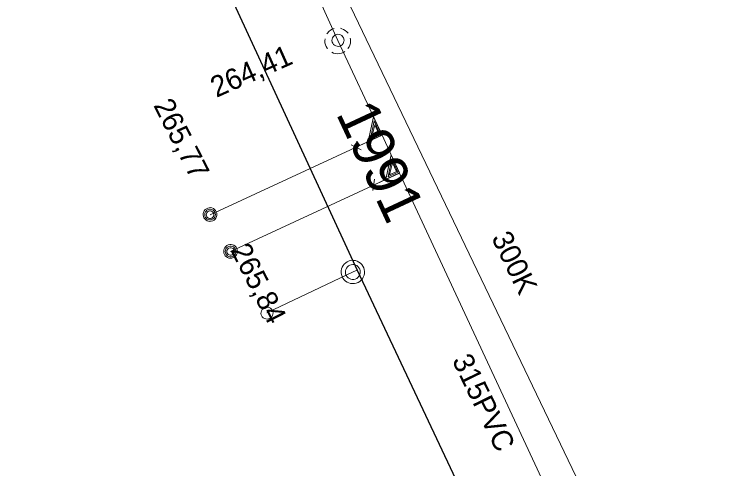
# Model space of a CAD drawing. Extents: x -732096 to -731933, y -1048703 to -1047964.
# Drawn here: x -732047.25 to -732019.99, y -1048499.57 to -1048482.15 of the extents above; entities that cross this region are included whole.
import ezdxf

# ---------------------------------------------------------------- set-up
doc = ezdxf.new("R2010")
doc.units = 0
doc.header["$LTSCALE"] = 0.32
doc.layers.add('1', color=7, linetype='Continuous')
for name, color, linetype, lineweight in [('18', 7, 'Continuous', 13), ('20', 7, 'Continuous', 13), ('49', 7, 'Continuous', 13), ('8', 7, 'Continuous', 13)]:
    doc.layers.add(name, color=color, linetype=linetype, lineweight=lineweight)

msp = doc.modelspace()

# ---------------------------------------------------------------- linework, layer by layer
at = {"layer": '18'}
for p, q in [((-732034.323, -1048487.152), (-732033.938, -1048487.342)), ((-732034.168, -1048487.454), (-732034.103, -1048487.015)), ((-732033.648, -1048488.603), (-732033.262, -1048488.794)), ((-732033.493, -1048488.905), (-732033.428, -1048488.466))]:
    msp.add_line(p, q, dxfattribs=at)
for points in [[(-732034.982, -1048482.697), (-732035.053, -1048482.725), (-732035.12, -1048482.764), (-732035.18, -1048482.812), (-732035.231, -1048482.869), (-732035.255, -1048482.903)], [(-732034.441, -1048482.88), (-732034.491, -1048482.822), (-732034.549, -1048482.772), (-732034.614, -1048482.731), (-732034.685, -1048482.702), (-732034.734, -1048482.688)], [(-732035.327, -1048483.089), (-732035.333, -1048483.166), (-732035.328, -1048483.243), (-732035.311, -1048483.318), (-732035.282, -1048483.389), (-732035.242, -1048483.455), (-732035.226, -1048483.477)], [(-732034.446, -1048483.466), (-732034.405, -1048483.401), (-732034.374, -1048483.331), (-732034.355, -1048483.256), (-732034.347, -1048483.18), (-732034.352, -1048483.103), (-732034.358, -1048483.068)], [(-732035.069, -1048483.606), (-732034.999, -1048483.637), (-732034.924, -1048483.656), (-732034.848, -1048483.663), (-732034.771, -1048483.658), (-732034.696, -1048483.641), (-732034.624, -1048483.613), (-732034.564, -1048483.578)], [(-732034.138, -1048487.244), (-732033.144, -1048486.781), (-732033.47, -1048486.082), (-732033.668, -1048487.025)], [(-732033.583, -1048486.929), (-732033.206, -1048486.753), (-732033.444, -1048486.241), (-732033.584, -1048486.929)], [(-732033.527, -1048486.851), (-732033.263, -1048486.728), (-732033.419, -1048486.392), (-732033.526, -1048486.853)], [(-732033.463, -1048488.695), (-732032.469, -1048488.232), (-732032.795, -1048487.533), (-732032.993, -1048488.476)], [(-732032.908, -1048488.38), (-732032.531, -1048488.204), (-732032.769, -1048487.692), (-732032.909, -1048488.381)], [(-732032.852, -1048488.302), (-732032.588, -1048488.179), (-732032.744, -1048487.843), (-732032.851, -1048488.304)]]:
    msp.add_lwpolyline(points, dxfattribs=at)
for points in [[(-732034.598, -1048483.149), (-732034.604, -1048483.097), (-732034.622, -1048483.047), (-732034.65, -1048483.003), (-732034.688, -1048482.966), (-732034.733, -1048482.939), (-732034.783, -1048482.923), (-732034.835, -1048482.918), (-732034.887, -1048482.925), (-732034.936, -1048482.944), (-732034.98, -1048482.974), (-732035.015, -1048483.013), (-732035.041, -1048483.058), (-732035.056, -1048483.109), (-732035.059, -1048483.161), (-732035.051, -1048483.213), (-732035.03, -1048483.261), (-732035, -1048483.304), (-732034.96, -1048483.339), (-732034.914, -1048483.363), (-732034.863, -1048483.377), (-732034.811, -1048483.379), (-732034.759, -1048483.369), (-732034.711, -1048483.347), (-732034.669, -1048483.315), (-732034.636, -1048483.275), (-732034.612, -1048483.228), (-732034.6, -1048483.177)], [(-732039.475, -1048489.827), (-732039.48, -1048489.771), (-732039.497, -1048489.718), (-732039.526, -1048489.669), (-732039.565, -1048489.628), (-732039.61, -1048489.596), (-732039.663, -1048489.574), (-732039.718, -1048489.563), (-732039.774, -1048489.565), (-732039.828, -1048489.578), (-732039.879, -1048489.603), (-732039.924, -1048489.638), (-732039.96, -1048489.681), (-732039.985, -1048489.731), (-732040, -1048489.786), (-732040.002, -1048489.842), (-732039.994, -1048489.897), (-732039.973, -1048489.95), (-732039.941, -1048489.996), (-732039.901, -1048490.035), (-732039.853, -1048490.065), (-732039.801, -1048490.084), (-732039.745, -1048490.091), (-732039.688, -1048490.087), (-732039.634, -1048490.07), (-732039.585, -1048490.043), (-732039.544, -1048490.005), (-732039.511, -1048489.96), (-732039.487, -1048489.909), (-732039.475, -1048489.854)], [(-732039.534, -1048489.83), (-732039.539, -1048489.781), (-732039.558, -1048489.735), (-732039.585, -1048489.694), (-732039.622, -1048489.661), (-732039.666, -1048489.639), (-732039.715, -1048489.627), (-732039.764, -1048489.627), (-732039.811, -1048489.639), (-732039.855, -1048489.662), (-732039.892, -1048489.695), (-732039.921, -1048489.736), (-732039.938, -1048489.783), (-732039.943, -1048489.832), (-732039.936, -1048489.881), (-732039.919, -1048489.927), (-732039.891, -1048489.967), (-732039.853, -1048490), (-732039.809, -1048490.022), (-732039.761, -1048490.034), (-732039.712, -1048490.033), (-732039.664, -1048490.021), (-732039.62, -1048489.997), (-732039.583, -1048489.964), (-732039.556, -1048489.923), (-732039.539, -1048489.876)], [(-732039.593, -1048489.834), (-732039.598, -1048489.792), (-732039.615, -1048489.754), (-732039.644, -1048489.723), (-732039.678, -1048489.7), (-732039.718, -1048489.689), (-732039.761, -1048489.689), (-732039.801, -1048489.701), (-732039.835, -1048489.724), (-732039.862, -1048489.756), (-732039.879, -1048489.794), (-732039.884, -1048489.835), (-732039.879, -1048489.877), (-732039.86, -1048489.914), (-732039.833, -1048489.946), (-732039.796, -1048489.968), (-732039.757, -1048489.979), (-732039.715, -1048489.978), (-732039.674, -1048489.965), (-732039.641, -1048489.942), (-732039.614, -1048489.909), (-732039.598, -1048489.871)], [(-732038.685, -1048491.237), (-732038.691, -1048491.181), (-732038.708, -1048491.128), (-732038.737, -1048491.079), (-732038.775, -1048491.038), (-732038.821, -1048491.006), (-732038.873, -1048490.984), (-732038.928, -1048490.973), (-732038.984, -1048490.975), (-732039.039, -1048490.988), (-732039.09, -1048491.013), (-732039.134, -1048491.048), (-732039.17, -1048491.091), (-732039.195, -1048491.141), (-732039.21, -1048491.196), (-732039.213, -1048491.252), (-732039.204, -1048491.307), (-732039.183, -1048491.36), (-732039.152, -1048491.406), (-732039.112, -1048491.445), (-732039.064, -1048491.475), (-732039.011, -1048491.494), (-732038.955, -1048491.501), (-732038.899, -1048491.497), (-732038.845, -1048491.48), (-732038.796, -1048491.453), (-732038.754, -1048491.415), (-732038.721, -1048491.37), (-732038.698, -1048491.319), (-732038.686, -1048491.264)], [(-732038.744, -1048491.24), (-732038.75, -1048491.191), (-732038.768, -1048491.145), (-732038.796, -1048491.104), (-732038.833, -1048491.071), (-732038.877, -1048491.049), (-732038.925, -1048491.037), (-732038.974, -1048491.037), (-732039.022, -1048491.049), (-732039.066, -1048491.072), (-732039.103, -1048491.105), (-732039.131, -1048491.146), (-732039.148, -1048491.193), (-732039.154, -1048491.242), (-732039.147, -1048491.291), (-732039.129, -1048491.337), (-732039.101, -1048491.377), (-732039.064, -1048491.41), (-732039.02, -1048491.432), (-732038.971, -1048491.444), (-732038.922, -1048491.443), (-732038.874, -1048491.431), (-732038.831, -1048491.407), (-732038.794, -1048491.374), (-732038.766, -1048491.333), (-732038.75, -1048491.286)], [(-732038.803, -1048491.244), (-732038.809, -1048491.202), (-732038.826, -1048491.164), (-732038.854, -1048491.133), (-732038.889, -1048491.11), (-732038.929, -1048491.099), (-732038.971, -1048491.099), (-732039.011, -1048491.111), (-732039.046, -1048491.134), (-732039.073, -1048491.166), (-732039.09, -1048491.204), (-732039.095, -1048491.245), (-732039.089, -1048491.287), (-732039.071, -1048491.324), (-732039.043, -1048491.356), (-732039.007, -1048491.378), (-732038.967, -1048491.389), (-732038.925, -1048491.388), (-732038.885, -1048491.375), (-732038.851, -1048491.352), (-732038.824, -1048491.319), (-732038.808, -1048491.281)]]:
    msp.add_lwpolyline(points, close=True, dxfattribs=at)
at = {"layer": '20'}
msp.add_line((-732020.46, -1048510.78), (-732038, -1048474.23), dxfattribs=at)
msp.add_line((-732020.46, -1048510.78), (-732038, -1048474.23), dxfattribs=at)
for points in [[(-732034.829, -1048483.16), (-732035.513, -1048481.657), (-732046.05, -1048458.48), (-732047.25, -1048455.84)], [(-732034.829, -1048483.16), (-732035.513, -1048481.657), (-732046.05, -1048458.48), (-732047.25, -1048455.84)], [(-732022.17, -1048510.34), (-732032.465, -1048488.236), (-732033.14, -1048486.786), (-732034.829, -1048483.16)], [(-732022.17, -1048510.34), (-732032.465, -1048488.236), (-732033.14, -1048486.786), (-732034.829, -1048483.16)]]:
    msp.add_lwpolyline(points, dxfattribs=at)
at = {"layer": '49'}
for p, q in [((-732039.739, -1048489.84), (-732033.14, -1048486.786)), ((-732039.739, -1048489.84), (-732033.14, -1048486.786)), ((-732038.949, -1048491.25), (-732032.465, -1048488.236)), ((-732038.949, -1048491.25), (-732032.465, -1048488.236))]:
    msp.add_line(p, q, dxfattribs=at)
at = {"layer": '8'}
for p, q in [((-732034.25, -1048492.03), (-732037.558, -1048493.594)), ((-732034.093, -1048491.956), (-732034.25, -1048492.03))]:
    msp.add_line(p, q, dxfattribs=at)
at = {"layer": '8', "lineweight": 25}
msp.add_lwpolyline([(-732043.199, -1048472.29), (-732042.854, -1048473.025), (-732034.093, -1048491.956), (-732023.079, -1048515.311), (-732013.932, -1048535.062), (-732012.27, -1048538.65), (-732009.129, -1048546.26)], dxfattribs=at)
at = {"layer": '8'}
for points in [[(-732034.26, -1048491.582), (-732034.333, -1048491.588), (-732034.404, -1048491.606), (-732034.471, -1048491.635), (-732034.532, -1048491.675), (-732034.587, -1048491.724), (-732034.632, -1048491.781), (-732034.667, -1048491.845), (-732034.692, -1048491.914), (-732034.705, -1048491.986), (-732034.706, -1048492.06), (-732034.695, -1048492.132), (-732034.672, -1048492.202), (-732034.639, -1048492.266), (-732034.595, -1048492.325), (-732034.542, -1048492.376), (-732034.482, -1048492.417), (-732034.415, -1048492.448), (-732034.345, -1048492.468), (-732034.272, -1048492.476), (-732034.199, -1048492.473), (-732034.128, -1048492.457), (-732034.06, -1048492.43), (-732033.997, -1048492.392), (-732033.942, -1048492.344), (-732033.895, -1048492.288), (-732033.858, -1048492.225), (-732033.831, -1048492.157), (-732033.816, -1048492.085), (-732033.813, -1048492.012), (-732033.822, -1048491.939), (-732033.843, -1048491.869), (-732033.875, -1048491.803), (-732033.917, -1048491.743), (-732033.968, -1048491.691), (-732034.028, -1048491.648), (-732034.093, -1048491.615), (-732034.163, -1048491.594), (-732034.235, -1048491.584)], [(-732034.26, -1048491.744), (-732034.318, -1048491.749), (-732034.374, -1048491.767), (-732034.425, -1048491.795), (-732034.469, -1048491.834), (-732034.505, -1048491.88), (-732034.53, -1048491.933), (-732034.544, -1048491.99), (-732034.546, -1048492.049), (-732034.536, -1048492.106), (-732034.514, -1048492.161), (-732034.482, -1048492.21), (-732034.441, -1048492.251), (-732034.392, -1048492.283), (-732034.337, -1048492.305), (-732034.28, -1048492.315), (-732034.221, -1048492.314), (-732034.164, -1048492.3), (-732034.111, -1048492.275), (-732034.065, -1048492.239), (-732034.026, -1048492.195), (-732033.998, -1048492.144), (-732033.98, -1048492.088), (-732033.974, -1048492.03), (-732033.98, -1048491.972), (-732033.997, -1048491.916), (-732034.026, -1048491.865), (-732034.065, -1048491.821), (-732034.111, -1048491.786), (-732034.164, -1048491.761), (-732034.221, -1048491.747)], [(-732037.762, -1048493.701), (-732037.734, -1048493.746), (-732037.697, -1048493.783), (-732037.653, -1048493.811), (-732037.603, -1048493.829), (-732037.55, -1048493.834), (-732037.498, -1048493.827), (-732037.449, -1048493.809), (-732037.405, -1048493.781), (-732037.369, -1048493.743), (-732037.342, -1048493.697), (-732037.327, -1048493.647), (-732037.322, -1048493.595), (-732037.331, -1048493.542), (-732037.35, -1048493.494), (-732037.379, -1048493.451), (-732037.419, -1048493.416), (-732037.464, -1048493.39), (-732037.515, -1048493.375), (-732037.567, -1048493.373), (-732037.619, -1048493.382), (-732037.667, -1048493.403), (-732037.71, -1048493.434), (-732037.744, -1048493.474), (-732037.769, -1048493.521), (-732037.781, -1048493.571), (-732037.783, -1048493.624), (-732037.772, -1048493.675)]]:
    msp.add_lwpolyline(points, close=True, dxfattribs=at)

# ---------------------------------------------------------------- texts
at = {"layer": '1'}
for s, height, rotation, p in [('264,41', 0.8, 24, (-732039.495, -1048485.357)), ('265,77', 0.8, 297, (-732041.924, -1048485.636)), ('1991', 1.6, 295, (-732034.922, -1048485.95)), ('300K', 0.8, 296, (-732028.959, -1048490.717)), ('265,84', 0.8, 297, (-732038.97, -1048491.183)), ('315PVC', 0.8, 296, (-732030.469, -1048495.415))]:
    msp.add_text(s, height=height, rotation=rotation, dxfattribs=at).set_placement(p)

doc.saveas('drawing.dxf')
